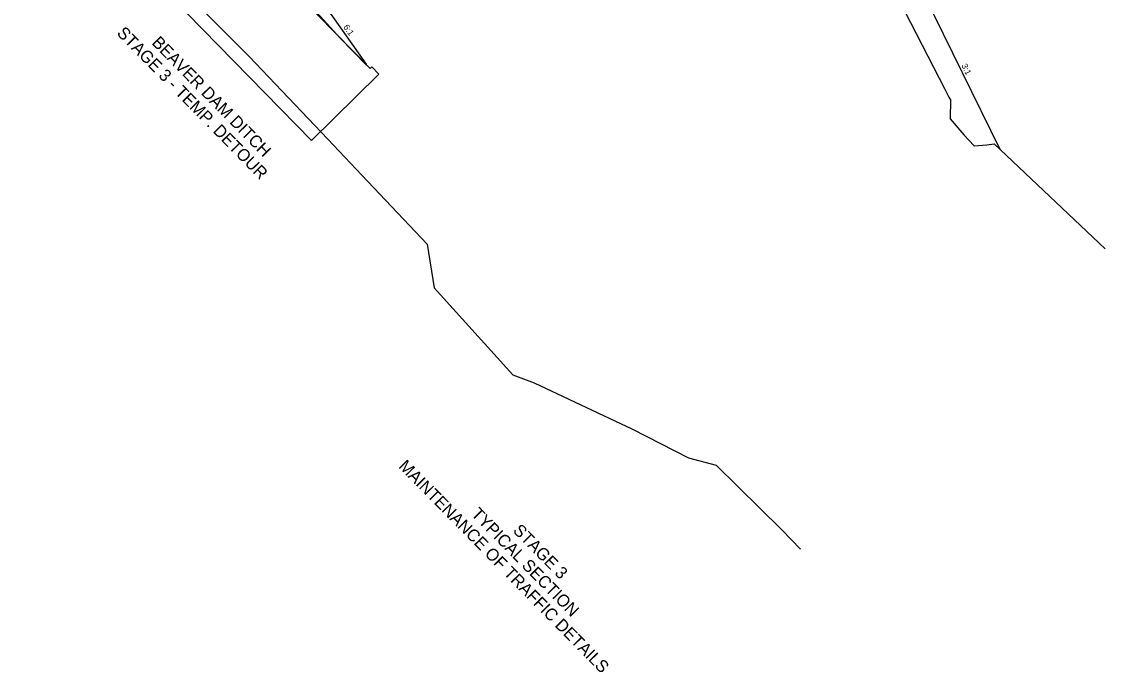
# Model space of a CAD drawing. Extents: x 1660305 to 1660468, y 670370 to 670550.
# Drawn here: x 1660339.9 to 1660447, y 670370 to 670434.3 of the extents above; entities that cross this region are included whole.
import ezdxf

# ---------------------------------------------------------------- set-up
doc = ezdxf.new("R2010")
doc.units = 0
for name, color, linetype in [('R_Annotation', 7, 'Continuous'), ('R_Exist Surface', 7, 'Continuous'), ('R_MOT', 7, 'Continuous')]:
    doc.layers.add(name, color=color, linetype=linetype)

msp = doc.modelspace()

# ---------------------------------------------------------------- linework, layer by layer
at = {"layer": 'R_Exist Surface'}
for points in [[(1660426.04, 670437.48), (1660431.11, 670427.6), (1660431.51, 670426.82), (1660431.67, 670426.56), (1660431.67, 670426.55), (1660431.64, 670424.67), (1660433.01, 670423.1), (1660434.01, 670422.01), (1660435.27, 670422.11), (1660435.99, 670422.19), (1660446.99, 670411.81)], [(1660356.34, 670436.86), (1660362.34, 670430.84), (1660370.14, 670422.65), (1660373.49, 670419.09), (1660379.96, 670412.27), (1660380.63, 670407.97), (1660388.43, 670399.36), (1660390.51, 670398.58), (1660400.25, 670393.99), (1660405.78, 670391.16), (1660408.51, 670390.43), (1660408.51, 670390.43), (1660415.02, 670384.05), (1660416.85, 670382.13)]]:
    msp.add_lwpolyline(points, dxfattribs=at)
at = {"layer": 'R_MOT'}
for p, q in [((1660374.3, 670429.64), (1660346.39, 670458.23)), ((1660339.86, 670451.86), (1660368.5, 670422.52)), ((1660371.35, 670432.66), (1660373.96, 670429.99)), ((1660374.3, 670429.64), (1660374.48, 670429.81)), ((1660374.48, 670429.81), (1660375.18, 670429.1)), ((1660368.5, 670422.52), (1660375.18, 670429.1))]:
    msp.add_line(p, q, dxfattribs=at)
for points in [[(1660399.08, 670469.1), (1660403.35, 670464.93), (1660406.27, 670462.19), (1660414.15, 670454.51), (1660421.71, 670446.52), (1660424.4, 670443.56), (1660428.72, 670437.41), (1660429.07, 670436.92), (1660436.55, 670421.66)], [(1660342.99, 670463.01), (1660343.23, 670462.77), (1660348.53, 670457.59), (1660351.45, 670454.86), (1660359.33, 670447.17), (1660366.89, 670439.18), (1660369.58, 670436.22), (1660373.9, 670430.07), (1660373.96, 670429.99)], [(1660347.76, 670456.83), (1660347.79, 670456.81), (1660350.71, 670454.07), (1660358.56, 670446.41), (1660366.1, 670438.44), (1660371.35, 670432.66)]]:
    msp.add_lwpolyline(points, dxfattribs=at)

# ---------------------------------------------------------------- texts
at = {"layer": 'R_Annotation'}
for s, height, rotation, p in [('6:1', 0.6, 305.0953, (1660371.63, 670433.74)), ('STAGE 3 - TEMP. DETOUR', 1.2, 314.5226, (1660349.19, 670433.07)), ('BEAVER DAM DITCH', 1.2, 314.5226, (1660352.65, 670432.12)), ('3:1', 0.6, 296.1227, (1660432.75, 670429.94)), ('MAINTENANCE OF TRAFFIC DETAILS', 1.2, 314.5576, (1660377.05, 670390.24)), ('TYPICAL SECTION', 1.2, 314.5576, (1660384.22, 670385.52)), ('STAGE 3', 1.2, 314.5576, (1660388.35, 670383.9))]:
    msp.add_text(s, height=height, rotation=rotation, dxfattribs=at).set_placement(p)

doc.saveas('drawing.dxf')
